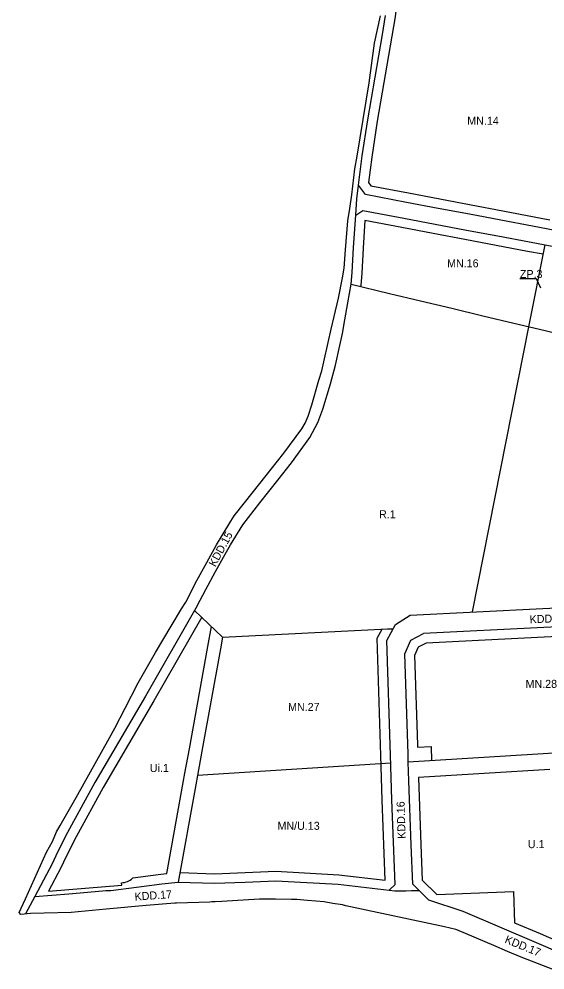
# Model space of a CAD drawing. Extents: x 7416945 to 7418410, y 5548550 to 5549803.
# Drawn here: x 7417044 to 7417372, y 5548688 to 5549282 of the extents above; entities that cross this region are included whole.
import ezdxf

# ---------------------------------------------------------------- set-up
doc = ezdxf.new("R2010")
doc.units = 0
for name, color, linetype in [('linie rozgraniczające', 7, 'Continuous'), ('nieprzekraczalne linie zabudowy', 7, 'Continuous'), ('przeznaczenia terenów', 7, 'Continuous')]:
    doc.layers.add(name, color=color, linetype=linetype)

msp = doc.modelspace()

# ---------------------------------------------------------------- linework, layer by layer
at = {"layer": 'linie rozgraniczające'}
for p, q in [((7417305.62, 5549163.65), (7417285.97, 5549167.37)), ((7417254.13, 5549159.4), (7417258.54, 5549162.41)), ((7417258.54, 5549162.41), (7417284.11, 5549157.57)), ((7417325.27, 5549159.93), (7417305.62, 5549163.65)), ((7417344.92, 5549156.2), (7417325.27, 5549159.93)), ((7417284.11, 5549157.57), (7417303.76, 5549153.84)), ((7417303.76, 5549153.84), (7417323.41, 5549150.13)), ((7417364.57, 5549152.5), (7417344.92, 5549156.2)), ((7417384.22, 5549148.78), (7417364.57, 5549152.5)), ((7417362.71, 5549142.67), (7417382.36, 5549138.96)), ((7417273.95, 5548900.78), (7417277.57, 5548900.96)), ((7417275.88, 5548821.81), (7417273.67, 5548893.56))]:
    msp.add_line(p, q, dxfattribs=at)
for points in [[(7417377.99, 5548687.66), (7417357.62, 5548695.58), (7417349.03, 5548699.28), (7417340.55, 5548702.89), (7417317.26, 5548712.79), (7417316.64, 5548713.06), (7417309.59, 5548714.57), (7417247.98, 5548727.81), (7417245.77, 5548728.29), (7417239.9, 5548729.3), (7417234.4, 5548730.24), (7417224.03, 5548731.17), (7417217.21, 5548731.77), (7417216.58, 5548731.78), (7417213.98, 5548731.79), (7417203.93, 5548731.86), (7417195.32, 5548731.93), (7417193.89, 5548731.85), (7417183.83, 5548731.28), (7417170.42, 5548730.52), (7417166.33, 5548730.29), (7417164.93, 5548730.21), (7417164.2, 5548730.17), (7417162.8, 5548730.1), (7417142.06, 5548729.37), (7417140.99, 5548729.34), (7417122.98, 5548727.95), (7417098.04, 5548725.58), (7417076.24, 5548723.51), (7417059.26, 5548723.12), (7417050.83, 5548722.96), (7417044.61, 5548722.33), (7417043.56, 5548723.62), (7417047.58, 5548732.17), (7417060.69, 5548761.34), (7417064.47, 5548767.98), (7417067.08, 5548774.02), (7417069.26, 5548777.95), (7417079.32, 5548795.56), (7417100.13, 5548832.74), (7417103.39, 5548838.84), (7417110.02, 5548851.27), (7417118.13, 5548867.09), (7417128.87, 5548886.16), (7417138.77, 5548902.54), (7417145.27, 5548913.4), (7417147.8, 5548917.61), (7417154.74, 5548931.02), (7417160.93, 5548942.28), (7417167.01, 5548953.3), (7417170.59, 5548959.17), (7417176.02, 5548968.08), (7417178.13, 5548971.49), (7417190.23, 5548986.68), (7417201.23, 5549000.58), (7417209.23, 5549010.71), (7417220.47, 5549025.8), (7417222.49, 5549029.45), (7417224.36, 5549033.82), (7417226.63, 5549040.79), (7417231.11, 5549056.18), (7417232.87, 5549062.15), (7417234.15, 5549067.67), (7417236.9, 5549079.81), (7417238.86, 5549088.2), (7417240.67, 5549095.98), (7417243.34, 5549107.53), (7417245.78, 5549120.32), (7417246.87, 5549126.28), (7417247.8, 5549137.73), (7417249.14, 5549155.92), (7417250.35, 5549163.49), (7417251.76, 5549172.02), (7417253.65, 5549188.33), (7417255.12, 5549196.29), (7417262.49, 5549242.13), (7417265.78, 5549266.8), (7417269.56, 5549284.01)], [(7417155.06, 5548915.31), (7417160.31, 5548925.47), (7417166.4, 5548936.67), (7417172.43, 5548947.61), (7417175.8, 5548953.31), (7417183.48, 5548965.86), (7417194.13, 5548979.54), (7417205.48, 5548993.86), (7417214.02, 5549004.67), (7417225.51, 5549020.4), (7417230.46, 5549029.9), (7417233.65, 5549038.1), (7417238.25, 5549053.89), (7417241.39, 5549065.7), (7417244.17, 5549077.96), (7417245.75, 5549085.54), (7417247.41, 5549094.06), (7417249.2, 5549104.56), (7417251.28, 5549116.27), (7417251.97, 5549123.67), (7417252.77, 5549139.12), (7417254.13, 5549159.4), (7417254.9, 5549169.52), (7417255.89, 5549178.17), (7417258.22, 5549196.39), (7417261.71, 5549219.04), (7417270.81, 5549272.22), (7417272.81, 5549284.16)], [(7417285.97, 5549167.37), (7417260.23, 5549172.26), (7417255.89, 5549178.17)], [(7417323.41, 5549150.13), (7417343.06, 5549146.4), (7417362.71, 5549142.67)], [(7417372.41, 5549140.84), (7417362.27, 5549089.68)], [(7417251.28, 5549116.27), (7417275.19, 5549110.54), (7417294.67, 5549105.88), (7417314.13, 5549101.21), (7417333.61, 5549096.55), (7417353.08, 5549091.88), (7417372.55, 5549087.23), (7417392.02, 5549082.56), (7417411.49, 5549077.9), (7417430.97, 5549073.25), (7417450.44, 5549068.58), (7417469.91, 5549063.92), (7417489.41, 5549059.41), (7417506.4, 5549055.48), (7417510.3, 5549054.58)], [(7417362.27, 5549089.68), (7417326.94, 5548911.41)], [(7417273.67, 5548893.56), (7417278.95, 5548903.58), (7417288.09, 5548909.49), (7417371.16, 5548913.6), (7417469.91, 5548918.46), (7417477.47, 5548924.85)], [(7417155.06, 5548915.31), (7417122.76, 5548858.86), (7417091.05, 5548804.78), (7417073.94, 5548773.68), (7417067.61, 5548761.22), (7417064.25, 5548754.1), (7417053.5, 5548733.48), (7417047.72, 5548722.65)], [(7417153.35, 5548912.32), (7417170.81, 5548895.68), (7417273.95, 5548900.78)], [(7417472.11, 5548900.55), (7417467.24, 5548906.31), (7417371.76, 5548901.6), (7417296.55, 5548897.89)], [(7417286.87, 5548822.49), (7417284.93, 5548885.3), (7417288.61, 5548893.76), (7417296.55, 5548897.89)], [(7417170.81, 5548895.68), (7417169.48, 5548888.34), (7417157.96, 5548824.51), (7417155.21, 5548809.3)], [(7417275.02, 5548737.52), (7417278.74, 5548740.99), (7417276.74, 5548794.03), (7417275.88, 5548821.81)], [(7417293.74, 5548737.31), (7417289.74, 5548741.2), (7417288.81, 5548765.87), (7417287.38, 5548805.95), (7417287.02, 5548817.49), (7417286.87, 5548822.49)], [(7417451.56, 5548814.61), (7417385.39, 5548815.89), (7417384.85, 5548823.57), (7417287.02, 5548817.49)], [(7417276.04, 5548816.81), (7417155.21, 5548809.3)], [(7417155.21, 5548809.3), (7417154.15, 5548803.41), (7417143.16, 5548742.57)], [(7417053.5, 5548733.48), (7417074.65, 5548735.29), (7417095.8, 5548737.09), (7417097.82, 5548737.25), (7417100.98, 5548737.4), (7417116.96, 5548739.46), (7417132.95, 5548741.53), (7417143.16, 5548742.57), (7417165.83, 5548741.84), (7417184.96, 5548742.61), (7417204.08, 5548743.37), (7417223.58, 5548742.3), (7417243.09, 5548741.23), (7417278.57, 5548737.11), (7417285.51, 5548737.2), (7417289.04, 5548737.33), (7417289.89, 5548737.32), (7417293.74, 5548737.31), (7417299.73, 5548731.48), (7417321.05, 5548724.47), (7417344.04, 5548714.7), (7417367.02, 5548704.93), (7417396.96, 5548691.82)]]:
    msp.add_lwpolyline(points, dxfattribs=at)
at = {"layer": 'nieprzekraczalne linie zabudowy'}
for points in [[(7417280.75, 5549300.59), (7417278.75, 5549283.32), (7417276.73, 5549271.22), (7417267.63, 5549218.08), (7417264.16, 5549195.55), (7417262.15, 5549179.79), (7417263.67, 5549177.71), (7417287.09, 5549173.26), (7417326.39, 5549165.83), (7417346.03, 5549162.1), (7417365.68, 5549158.4), (7417375.51, 5549156.54)], [(7417371.24, 5549134.95), (7417361.59, 5549136.77), (7417322.29, 5549144.23), (7417302.64, 5549147.94), (7417282.99, 5549151.67), (7417259.92, 5549156.04), (7417258.76, 5549138.77), (7417257.96, 5549123.23), (7417257.23, 5549115.47), (7417257.13, 5549114.87)], [(7417157.82, 5548908.06), (7417127.95, 5548855.85), (7417096.27, 5548801.81), (7417079.25, 5548770.87), (7417073, 5548758.58), (7417069.63, 5548751.43), (7417062.04, 5548736.89), (7417107.79, 5548740.67), (7417107.67, 5548742.18), (7417108.52, 5548742.26), (7417109.56, 5548742.43), (7417110.52, 5548742.68), (7417111.35, 5548742.94), (7417112.19, 5548743.31), (7417113.07, 5548743.73), (7417113.99, 5548744.48), (7417114.81, 5548745.24), (7417132.26, 5548747.49), (7417135.99, 5548747.87), (7417146.28, 5548804.83), (7417147.34, 5548810.72), (7417150.09, 5548825.93), (7417161.61, 5548889.76), (7417163.88, 5548902.29)], [(7417144.24, 5548748.54), (7417165.81, 5548747.84), (7417204.12, 5548749.38), (7417243.6, 5548747.21), (7417272.63, 5548743.84), (7417270.74, 5548793.83), (7417269.88, 5548821.62), (7417267.63, 5548894.96), (7417270.61, 5548900.61)], [(7417441.31, 5548814.81), (7417441.85, 5548816.99), (7417451.42, 5548856.04), (7417457.85, 5548882.34), (7417461.75, 5548900.04), (7417372.05, 5548895.61), (7417298.16, 5548891.96), (7417293.26, 5548889.42), (7417290.97, 5548884.14), (7417292.69, 5548828.47), (7417292.73, 5548826.87), (7417301.25, 5548827.4), (7417301.53, 5548818.39)], [(7417375.57, 5548812.97), (7417293.31, 5548807.86)], [(7417293.31, 5548807.86), (7417294.81, 5548766.09), (7417295.65, 5548743.83), (7417304.92, 5548734.8), (7417352.7, 5548736.61), (7417353.44, 5548717.22), (7417369.4, 5548710.44), (7417399.35, 5548697.32)]]:
    msp.add_lwpolyline(points, dxfattribs=at)
at = {"layer": 'przeznaczenia terenów'}
msp.add_lwpolyline([(7417356.85, 5549119.87), (7417366.9, 5549119.87), (7417369.65, 5549114.08)], dxfattribs=at)

# ---------------------------------------------------------------- texts
for s, p in [('MN.14', (7417323.88, 5549215.9)), ('MN.16', (7417311.25, 5549126.83)), ('ZP.3', (7417356.78, 5549120.15)), ('R.1', (7417268.72, 5548969.97)), ('MN.28', (7417360.34, 5548863.98)), ('MN.27', (7417211.82, 5548849.56)), ('Ui.1', (7417125.38, 5548811.38)), ('MN/U.13', (7417205.21, 5548775.26)), ('U.1', (7417361.77, 5548763.81))]:
    msp.add_text(s, height=5, dxfattribs=at).set_placement(p)
for s, rotation, p in [('KDD.15', 61.88071, (7417166.33, 5548939.22)), ('KDD.16', 2.25727, (7417362.96, 5548904.3)), ('KDD.16', 91.82339, (7417285.37, 5548769.73)), ('KDD.17', 3.81049, (7417115.99, 5548731.01)), ('KDD.17', 337.81259, (7417346.9, 5548704.82))]:
    msp.add_text(s, height=5, rotation=rotation, dxfattribs=at).set_placement(p)

doc.saveas('drawing.dxf')
